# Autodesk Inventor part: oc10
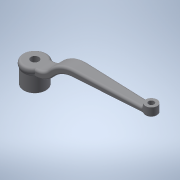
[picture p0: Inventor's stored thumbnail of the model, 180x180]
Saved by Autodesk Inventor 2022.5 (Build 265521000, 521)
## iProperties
Created: 2016-12
Part Number: oc10
Material: 一般
Document SubType Name: Modeling
Designer: imaocorp
Density: 1 g/cm^3
Appearance: 既定
Author: imaocorp
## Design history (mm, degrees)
node "oc10.x_t1"
node "oc10"
node "Base1"
